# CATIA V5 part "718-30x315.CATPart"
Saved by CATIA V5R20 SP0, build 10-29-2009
Part number: 718-30x315
Definition: NONE
Nomenclature: 718-30x315
Source: Unknown
Description: 718-30x315
Bounding box of the stored display mesh (mm): x 0 to 352, y -20 to 20, z -20 to 20
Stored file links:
  C:\Users\Utente\Desktop\IO LAVORO\3D X SITO CF\X SITO\3D files 718\3D files 718\718-30x315.CATPart
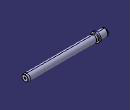
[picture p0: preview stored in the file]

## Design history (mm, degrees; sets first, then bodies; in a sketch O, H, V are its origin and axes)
Body1 "718-30x315" (main body)
  Solid1: solid without history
